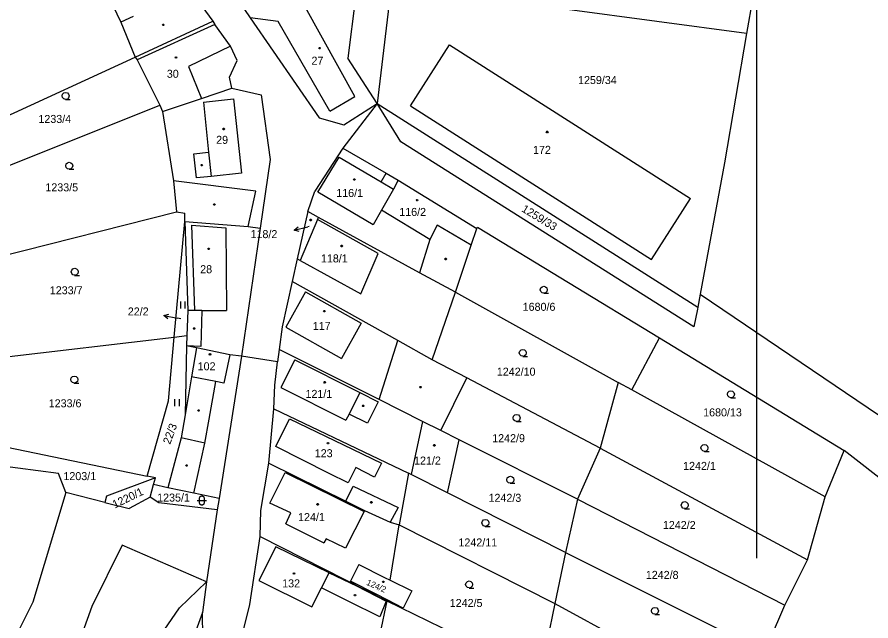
# Model space of a CAD drawing. Extents: x -802857 to -799647, y -1020285 to -1015884.
# Drawn here: x -801407 to -801225.7, y -1018013.3 to -1017885.2 of the extents above; entities that cross this region are included whole.
import ezdxf

# ---------------------------------------------------------------- set-up
doc = ezdxf.new("R2010")
doc.units = 0
for name, color, linetype in [('Default', 7, 'Continuous'), ('KLADY_ZMVM', 7, 'Continuous'), ('KN_HRANICE', 7, 'Continuous'), ('KN_KULTURY', 7, 'Continuous'), ('KN_PARCELY', 7, 'Continuous'), ('KN_SLUCKY', 7, 'Continuous')]:
    doc.layers.add(name, color=color, linetype=linetype)

# ---------------------------------------------------------------- blocks, each defined once
blk = doc.blocks.new('304')
at = {"layer": 'Default'}
blk.add_lwpolyline([(0, 0), (-0.38, 0.1), (-0.65, 0.37), (-0.75, 0.74), (-0.65, 1.11), (-0.38, 1.38), (-0.01, 1.48), (0.36, 1.38), (0.63, 1.11), (0.73, 0.73), (0.63, 0.35), (0.36, 0.08), (-0.02, -0.02), (0.98, -0.02)], dxfattribs=at)
blk = doc.blocks.new('306')
at = {"layer": 'Default'}
for p, q in [((-0.5, 1.5), (-0.5, 0)), ((0.5, 0), (0.5, 1.5))]:
    blk.add_line(p, q, dxfattribs=at)
blk = doc.blocks.new('316')
at = {"layer": 'Default'}
for points in [[(-0.5, 1.5), (-0.4, 1.79), (-0.15, 1.97), (0.16, 1.97), (0.41, 1.79), (0.51, 1.5), (0.51, 0.5), (0.41, 0.21), (0.16, 0.03), (-0.15, 0.03), (-0.4, 0.21), (-0.5, 0.5), (-0.5, 1.5)], [(-1, 1), (0.27, 1), (1, 1)]]:
    blk.add_lwpolyline(points, dxfattribs=at)
blk = doc.blocks.new('NAHRADNI_SYMBOL')
at = {"layer": 'Default'}
blk.add_lwpolyline([(0.09, 0.15), (0.18, 0), (0.09, -0.15), (-0.09, -0.15), (-0.18, 0), (-0.09, 0.15), (0.09, 0.15)], dxfattribs=at)
blk = doc.blocks.new('10292')
at = {"layer": 'Default'}
blk.add_line((0, 3), (0, 0), dxfattribs=at)
blk.add_lwpolyline([(-0.5, 2), (0, 3), (0.5, 2)], dxfattribs=at)
blk = doc.blocks.new('402')
at = {"layer": 'Default'}
blk.add_lwpolyline([(0.09, 0.15), (0.18, 0), (0.09, -0.15), (-0.09, -0.15), (-0.18, 0), (-0.09, 0.15), (0.09, 0.15)], dxfattribs=at)

msp = doc.modelspace()

# ---------------------------------------------------------------- linework, layer by layer
at = {"layer": 'KLADY_ZMVM'}
msp.add_lwpolyline([(-801250, -1017000), (-801250, -1017500), (-801250, -1018000)], dxfattribs=at)
at = {"layer": 'KN_HRANICE'}
for p, q in [((-801333.53, -1017868.36), (-801336.82, -1017893.87)), ((-801249.45, -1017873.01), (-801252.11, -1017888.65)), ((-801327.56, -1017878.51), (-801330.54, -1017903.51)), ((-801252.11, -1017888.65), (-801327.56, -1017878.51)), ((-801387.94, -1017879.91), (-801384.99, -1017886.23)), ((-801370.22, -1017879.44), (-801365.46, -1017886.06)), ((-801358.71, -1017883.58), (-801357.53, -1017885.3)), ((-801384.99, -1017886.23), (-801381.92, -1017893.65)), ((-801365.46, -1017886.06), (-801365.03, -1017886.71)), ((-801357.53, -1017885.3), (-801342.89, -1017906.53)), ((-801365.03, -1017886.71), (-801381.54, -1017894.26)), ((-801361.74, -1017891.36), (-801365.03, -1017886.71)), ((-801252.11, -1017888.65), (-801256.79, -1017916.12)), ((-801360.26, -1017894.37), (-801361.74, -1017891.36)), ((-801323.48, -1017904.01), (-801315.22, -1017891.06)), ((-801315.22, -1017891.06), (-801264.04, -1017923.7)), ((-801414.45, -1017908.61), (-801381.92, -1017893.65)), ((-801381.92, -1017893.65), (-801381.54, -1017894.26)), ((-801381.54, -1017894.26), (-801376.7, -1017903.9)), ((-801361.91, -1017897.94), (-801360.26, -1017894.37)), ((-801330.54, -1017903.51), (-801336.82, -1017893.87)), ((-801361.41, -1017900.25), (-801361.91, -1017897.94)), ((-801367.85, -1017902.42), (-801361.41, -1017900.25)), ((-801361.41, -1017900.25), (-801355.21, -1017901.66)), ((-801376.18, -1017905.18), (-801367.85, -1017902.42)), ((-801355.21, -1017901.66), (-801353.31, -1017915.4)), ((-801416.02, -1017919.61), (-801376.7, -1017903.9)), ((-801376.7, -1017903.9), (-801376.18, -1017905.18)), ((-801330.54, -1017903.51), (-801337.83, -1017912.98)), ((-801337.61, -1017908.03), (-801330.54, -1017903.51)), ((-801325.53, -1017911.62), (-801330.54, -1017903.51)), ((-801330.54, -1017903.51), (-801262.48, -1017946.77)), ((-801323.48, -1017904.01), (-801272.3, -1017936.65)), ((-801376.18, -1017905.18), (-801373.8, -1017919.91)), ((-801342.89, -1017906.53), (-801337.61, -1017908.03)), ((-801263.28, -1017950.94), (-801325.53, -1017911.62)), ((-801337.83, -1017912.98), (-801343.79, -1017922.09)), ((-801337.83, -1017912.98), (-801328.66, -1017918.31)), ((-801353.31, -1017915.4), (-801355.42, -1017929.99)), ((-801256.79, -1017916.12), (-801261.98, -1017943.96)), ((-801329.74, -1017920.15), (-801328.66, -1017918.31)), ((-801328.66, -1017918.31), (-801326.07, -1017919.82)), ((-801373.8, -1017919.91), (-801373.19, -1017926.53)), ((-801329.74, -1017920.15), (-801327.1, -1017921.71)), ((-801326.07, -1017919.82), (-801309.37, -1017930.06)), ((-801345.31, -1017926.43), (-801343.79, -1017922.09)), ((-801327.1, -1017921.71), (-801329.63, -1017926.15)), ((-801272.3, -1017936.65), (-801264.04, -1017923.7)), ((-801319.36, -1017932.37), (-801329.63, -1017926.15)), ((-801417.56, -1017937.72), (-801373.19, -1017926.53)), ((-801373.19, -1017926.53), (-801371.41, -1017926.77)), ((-801371.42, -1017928.53), (-801371.41, -1017926.77)), ((-801345.31, -1017926.43), (-801347.54, -1017936.5)), ((-801343.21, -1017928.17), (-801346.9, -1017936.85)), ((-801342.99, -1017927.7), (-801345.31, -1017926.43)), ((-801343.21, -1017928.17), (-801342.99, -1017927.7)), ((-801321.54, -1017939.43), (-801342.99, -1017927.7)), ((-801373.64, -1017953.09), (-801371.42, -1017928.53)), ((-801371.42, -1017928.53), (-801357.93, -1017929.6)), ((-801371.42, -1017928.53), (-801370.74, -1017947.44)), ((-801355.42, -1017929.99), (-801359.36, -1017957.14)), ((-801357.93, -1017929.6), (-801355.42, -1017929.99)), ((-801317.8, -1017929.31), (-801319.36, -1017932.37)), ((-801310.57, -1017933.62), (-801317.8, -1017929.31)), ((-801309.37, -1017930.06), (-801309.25, -1017929.73)), ((-801309.25, -1017929.73), (-801270.61, -1017953.27)), ((-801310.57, -1017933.62), (-801309.37, -1017930.06)), ((-801313.94, -1017943.59), (-801310.57, -1017933.62)), ((-801347.54, -1017936.5), (-801348.61, -1017941.32)), ((-801346.9, -1017936.85), (-801347.54, -1017936.5)), ((-801313.94, -1017943.59), (-801321.54, -1017939.43)), ((-801348.61, -1017941.32), (-801350.73, -1017950.9)), ((-801326.17, -1017953.84), (-801348.61, -1017941.32)), ((-801318.88, -1017957.91), (-801313.94, -1017943.59)), ((-801313.94, -1017943.59), (-801279.37, -1017962.72)), ((-801261.98, -1017943.96), (-801262.48, -1017946.77)), ((-801261.98, -1017943.96), (-801198.39, -1017987.04)), ((-801370.74, -1017947.44), (-801370.95, -1017952.78)), ((-801262.55, -1017947.15), (-801263.28, -1017950.94)), ((-801262.48, -1017946.77), (-801262.55, -1017947.15)), ((-801350.73, -1017950.9), (-801351.38, -1017955.73)), ((-801419.31, -1017958.41), (-801373.64, -1017953.09)), ((-801374.87, -1017966.64), (-801373.64, -1017953.09)), ((-801373.64, -1017953.09), (-801370.95, -1017952.78)), ((-801370.95, -1017952.78), (-801371.03, -1017954.93)), ((-801276.5, -1017964.31), (-801270.61, -1017953.27)), ((-801270.61, -1017953.27), (-801231.39, -1017977.16)), ((-801371.03, -1017954.93), (-801371.36, -1017969.59)), ((-801368.92, -1017955.35), (-801371.03, -1017954.93)), ((-801361.84, -1017956.87), (-801368.92, -1017955.35)), ((-801318.88, -1017957.91), (-801326.17, -1017953.84)), ((-801359.36, -1017957.14), (-801364.13, -1017987.34)), ((-801359.36, -1017957.14), (-801361.84, -1017956.87)), ((-801351.73, -1017958.32), (-801359.36, -1017957.14)), ((-801351.38, -1017955.73), (-801351.73, -1017958.32)), ((-801330.17, -1017966.36), (-801351.38, -1017955.73)), ((-801352.32, -1017963.31), (-801351.73, -1017958.32)), ((-801311.5, -1017961.78), (-801318.88, -1017957.91)), ((-801317.05, -1017972.94), (-801311.5, -1017961.78)), ((-801283.17, -1017976.65), (-801311.5, -1017961.78)), ((-801352.51, -1017968.31), (-801352.32, -1017963.31)), ((-801279.37, -1017962.72), (-801283.17, -1017976.65)), ((-801276.5, -1017964.31), (-801279.37, -1017962.72)), ((-801235.44, -1017987.03), (-801276.5, -1017964.31)), ((-801379.38, -1017982.63), (-801374.87, -1017966.64)), ((-801320.94, -1017970.99), (-801330.17, -1017966.36)), ((-801371.36, -1017969.59), (-801372.21, -1017974.52)), ((-801353.58, -1017979.89), (-801352.51, -1017968.31)), ((-801352.51, -1017968.31), (-801323.93, -1017982)), ((-801320.94, -1017970.99), (-801323.35, -1017982.29)), ((-801317.05, -1017972.94), (-801320.94, -1017970.99)), ((-801313.17, -1017974.89), (-801317.05, -1017972.94)), ((-801420.83, -1017974.05), (-801379.38, -1017982.63)), ((-801372.21, -1017974.52), (-801375.02, -1017985.09)), ((-801315.64, -1017986.18), (-801313.17, -1017974.89)), ((-801288.02, -1017987.5), (-801313.17, -1017974.89)), ((-801283.17, -1017976.65), (-801288.02, -1017987.5)), ((-801283.17, -1017976.65), (-801239.16, -1018000.38)), ((-801235.44, -1017987.03), (-801231.39, -1017977.16)), ((-801209.9, -1017994.03), (-801231.39, -1017977.16)), ((-801398.22, -1017982.04), (-801421.32, -1017979.03)), ((-801355.23, -1017989.94), (-801353.58, -1017979.89)), ((-801353.58, -1017979.89), (-801337.21, -1017987.91)), ((-801396.64, -1017986.09), (-801398.22, -1017982.04)), ((-801323.93, -1017982), (-801325.88, -1017992.98)), ((-801323.35, -1017982.29), (-801323.93, -1017982)), ((-801315.64, -1017986.18), (-801323.35, -1017982.29)), ((-801377.64, -1017982.98), (-801388.03, -1017986.86)), ((-801377.64, -1017982.98), (-801379.38, -1017982.63)), ((-801378.76, -1017987.09), (-801378.04, -1017984.42)), ((-801378.04, -1017984.42), (-801377.64, -1017982.98)), ((-801375.02, -1017985.09), (-801378.04, -1017984.42)), ((-801396.64, -1017986.09), (-801403.7, -1018009.39)), ((-801388.4, -1017988.19), (-801396.64, -1017986.09)), ((-801369.47, -1017986.2), (-801375.02, -1017985.09)), ((-801364.13, -1017987.34), (-801369.47, -1017986.2)), ((-801290.6, -1017998.81), (-801315.64, -1017986.18)), ((-801388.03, -1017986.86), (-801388.4, -1017988.19)), ((-801378.76, -1017987.09), (-801383.2, -1017989.51)), ((-801376.96, -1017988.29), (-801378.76, -1017987.09)), ((-801364.13, -1017987.34), (-801364.52, -1017989.8)), ((-801337.21, -1017987.91), (-801333.24, -1017989.93)), ((-801288.02, -1017987.5), (-801290.6, -1017998.81)), ((-801288.02, -1017987.5), (-801243.96, -1018010)), ((-801239.16, -1018000.38), (-801235.44, -1017987.03)), ((-801388.4, -1017988.19), (-801383.2, -1017989.51)), ((-801364.52, -1017989.8), (-801376.96, -1017988.29)), ((-801364.52, -1017989.8), (-801366.8, -1018005.03)), ((-801355.39, -1017995.42), (-801355.23, -1017989.94)), ((-801333.24, -1017989.93), (-801327.78, -1017992.36)), ((-801327.78, -1017992.36), (-801325.88, -1017992.98)), ((-801327.78, -1018004.7), (-801325.88, -1017992.98)), ((-801325.88, -1017992.98), (-801292.85, -1018009.68)), ((-801357.6, -1018009.88), (-801355.39, -1017995.42)), ((-801355.39, -1017995.42), (-801328.49, -1018009.09)), ((-801384.72, -1017997.28), (-801391.12, -1018010.28)), ((-801366.8, -1018005.03), (-801384.72, -1017997.28)), ((-801290.6, -1017998.81), (-801292.85, -1018009.68)), ((-801290.6, -1017998.81), (-801248.25, -1018019.94)), ((-801243.96, -1018010), (-801239.16, -1018000.38)), ((-801334.42, -1018001.35), (-801336.22, -1018004.93)), ((-801334.42, -1018001.35), (-801328.98, -1018004.1)), ((-801328.98, -1018004.1), (-801327.78, -1018004.7)), ((-801372.53, -1018010.6), (-801366.8, -1018005.03)), ((-801366.8, -1018005.03), (-801367.65, -1018011.57)), ((-801330.78, -1018007.67), (-801336.22, -1018004.93)), ((-801327.78, -1018004.7), (-801323.22, -1018006.97)), ((-801328.46, -1018008.88), (-801330.78, -1018007.67)), ((-801323.22, -1018006.97), (-801325.07, -1018010.63)), ((-801403.7, -1018009.39), (-801421.73, -1018045.46)), ((-801328.49, -1018009.09), (-801329.99, -1018016.14)), ((-801328.49, -1018009.09), (-801328.46, -1018008.88)), ((-801328.49, -1018009.09), (-801295.95, -1018024.91)), ((-801325.07, -1018010.63), (-801328.46, -1018008.88)), ((-801292.85, -1018009.68), (-801295.95, -1018024.91)), ((-801292.85, -1018009.68), (-801252.58, -1018031.49)), ((-801391.12, -1018010.28), (-801402.79, -1018042.66)), ((-801384.44, -1018027.77), (-801372.53, -1018010.6)), ((-801367.65, -1018011.57), (-801380.88, -1018048.02)), ((-801367.61, -1018016.94), (-801367.65, -1018011.57)), ((-801360.46, -1018021.5), (-801357.6, -1018009.88)), ((-801248.25, -1018019.94), (-801243.96, -1018010))]:
    msp.add_line(p, q, dxfattribs=at)
at = {"layer": 'KN_PARCELY'}
for p, q in [((-801344.98, -1017929.64), (-801345.28, -1017929.71)), ((-801372.24, -1017949.24), (-801372.94, -1017949.1))]:
    msp.add_line(p, q, dxfattribs=at)
at = {"layer": 'KN_SLUCKY'}
for p, q in [((-801335.32, -1017902), (-801345.75, -1017883.16)), ((-801382.41, -1017885.03), (-801384.99, -1017886.23)), ((-801381.92, -1017893.65), (-801365.46, -1017886.06)), ((-801351.55, -1017886.13), (-801357.53, -1017885.3)), ((-801340.59, -1017905.11), (-801351.55, -1017886.13)), ((-801361.74, -1017891.36), (-801370.6, -1017895.68)), ((-801370.6, -1017895.68), (-801367.85, -1017902.42)), ((-801367.47, -1017903.23), (-801361.05, -1017902.52)), ((-801361.05, -1017902.52), (-801359.4, -1017918.31)), ((-801340.59, -1017905.11), (-801335.32, -1017902)), ((-801367.47, -1017903.23), (-801366.36, -1017913.86)), ((-801369.48, -1017914.19), (-801366.36, -1017913.86)), ((-801368.95, -1017919.31), (-801369.48, -1017914.19)), ((-801366.36, -1017913.86), (-801365.82, -1017918.98)), ((-801343.14, -1017922.3), (-801338.66, -1017914.88)), ((-801338.66, -1017914.88), (-801329.74, -1017920.15)), ((-801365.82, -1017918.98), (-801368.95, -1017919.31)), ((-801359.4, -1017918.31), (-801365.82, -1017918.98)), ((-801356.36, -1017922.11), (-801373.8, -1017919.91)), ((-801326.07, -1017919.82), (-801327.1, -1017921.71)), ((-801357.93, -1017929.6), (-801356.36, -1017922.11)), ((-801331.42, -1017929.24), (-801343.14, -1017922.3)), ((-801329.63, -1017926.15), (-801331.42, -1017929.24)), ((-801330.33, -1017935.36), (-801343.21, -1017928.17)), ((-801369.97, -1017929.35), (-801362.72, -1017929.9)), ((-801369.97, -1017929.35), (-801369.36, -1017947.45)), ((-801362.72, -1017929.9), (-801362.59, -1017947.45)), ((-801319.36, -1017932.37), (-801321.54, -1017939.43)), ((-801334, -1017943.9), (-801330.33, -1017935.36)), ((-801346.9, -1017936.85), (-801334, -1017943.9)), ((-801345.81, -1017943.46), (-801349.97, -1017950.96)), ((-801345.81, -1017943.46), (-801333.95, -1017950.12)), ((-801369.36, -1017947.45), (-801370.74, -1017947.44)), ((-801367.8, -1017947.47), (-801369.36, -1017947.45)), ((-801367.8, -1017947.47), (-801368.03, -1017955.07)), ((-801367.8, -1017947.47), (-801362.59, -1017947.45)), ((-801349.97, -1017950.96), (-801338.11, -1017957.62)), ((-801333.95, -1017950.12), (-801338.11, -1017957.62)), ((-801368.03, -1017955.07), (-801371.03, -1017954.93)), ((-801368.92, -1017955.35), (-801369.98, -1017961.56)), ((-801330.17, -1017966.36), (-801326.17, -1017953.84)), ((-801361.84, -1017956.87), (-801363.1, -1017962.87)), ((-801348.05, -1017957.96), (-801351.05, -1017963.8)), ((-801348.05, -1017957.96), (-801334.27, -1017964.86)), ((-801369.98, -1017961.56), (-801371.36, -1017969.59)), ((-801364.8, -1017962.55), (-801369.98, -1017961.56)), ((-801366.26, -1017970.53), (-801364.8, -1017962.55)), ((-801363.1, -1017962.87), (-801364.8, -1017962.55)), ((-801351.05, -1017963.8), (-801337.19, -1017970.74)), ((-801334.27, -1017964.86), (-801336.54, -1017969.43)), ((-801334.27, -1017964.86), (-801330.32, -1017966.84)), ((-801330.32, -1017966.84), (-801332.6, -1017971.4)), ((-801336.54, -1017969.43), (-801337.19, -1017970.74)), ((-801332.6, -1017971.4), (-801336.54, -1017969.43)), ((-801367.19, -1017975.61), (-801366.26, -1017970.53)), ((-801352.09, -1017976.3), (-801349.15, -1017970.42)), ((-801349.15, -1017970.42), (-801337.69, -1017975.98)), ((-801367.19, -1017975.61), (-801372.21, -1017974.52)), ((-801369.47, -1017986.2), (-801367.19, -1017975.61)), ((-801340.76, -1017982.03), (-801352.09, -1017976.3)), ((-801337.69, -1017975.98), (-801329.66, -1017979.87)), ((-801329.66, -1017979.87), (-801331.16, -1017982.8)), ((-801353.36, -1017988.32), (-801350.11, -1017981.87)), ((-801350.11, -1017981.87), (-801333.33, -1017990.11)), ((-801336.74, -1017984.06), (-801340.76, -1017982.03)), ((-801335.11, -1017980.8), (-801336.74, -1017984.06)), ((-801331.16, -1017982.8), (-801335.11, -1017980.8)), ((-801337.21, -1017987.91), (-801335.63, -1017984.73)), ((-801335.63, -1017984.73), (-801326.12, -1017989.25)), ((-801348.9, -1017990.41), (-801353.36, -1017988.32)), ((-801326.12, -1017989.25), (-801327.78, -1017992.36)), ((-801349.97, -1017992.75), (-801348.9, -1017990.41)), ((-801333.33, -1017990.11), (-801337.28, -1017997.9)), ((-801349.97, -1017992.75), (-801345.71, -1017994.87)), ((-801345.71, -1017994.87), (-801341.88, -1017996.78)), ((-801341.42, -1017995.92), (-801341.88, -1017996.78)), ((-801337.28, -1017997.9), (-801341.42, -1017995.92)), ((-801352.07, -1017997.62), (-801355.72, -1018004.74)), ((-801340.74, -1018003.13), (-801352.07, -1017997.62)), ((-801342.37, -1018006.35), (-801340.74, -1018003.13)), ((-801340.74, -1018003.13), (-801334.97, -1018005.93)), ((-801355.72, -1018004.74), (-801344.44, -1018010.35)), ((-801334.97, -1018005.93), (-801328.64, -1018009.13)), ((-801344.44, -1018010.35), (-801342.37, -1018006.35)), ((-801336.6, -1018009.2), (-801342.37, -1018006.35)), ((-801329.97, -1018012.48), (-801336.6, -1018009.2)), ((-801328.64, -1018009.13), (-801329.97, -1018012.48))]:
    msp.add_line(p, q, dxfattribs=at)

# ---------------------------------------------------------------- block references
at = {"layer": 'KN_KULTURY'}
for name, p in [('402', (-801375.99, -1017886.81)), ('402', (-801342.8, -1017891.76)), ('402', (-801373.27, -1017893.72)), ('304', (-801396.71, -1017902.64)), ('402', (-801363.17, -1017908.92)), ('402', (-801294.46, -1017909.56)), ('304', (-801395.94, -1017917.46)), ('402', (-801367.81, -1017916.59)), ('402', (-801335.39, -1017919.64)), ('402', (-801322.07, -1017924.01)), ('402', (-801365.15, -1017924.93)), ('NAHRADNI_SYMBOL', (-801344.7, -1017928.24)), ('402', (-801338.1, -1017933.77)), ('402', (-801366.36, -1017934.37)), ('402', (-801316, -1017936.53)), ('304', (-801394.78, -1017939.97)), ('304', (-801295.17, -1017943.78)), ('306', (-801371.85, -1017947.05)), ('402', (-801341.78, -1017947.62)), ('402', (-801369.42, -1017951.29)), ('402', (-801366.05, -1017956.76)), ('304', (-801299.63, -1017957.18)), ('304', (-801394.86, -1017962.85)), ('402', (-801341.68, -1017962.7)), ('402', (-801321.36, -1017963.73)), ('306', (-801373.07, -1017967.79)), ('304', (-801255.44, -1017965.97)), ('402', (-801333.53, -1017967.69)), ('402', (-801368.49, -1017968.66)), ('304', (-801300.94, -1017971)), ('402', (-801340.99, -1017975.62)), ('402', (-801318.43, -1017976.08)), ('304', (-801261.04, -1017977.36)), ('402', (-801371.04, -1017980.37)), ('304', (-801302.27, -1017984.11)), ('316', (-801367.81, -1017988.8)), ('402', (-801331.79, -1017988.17)), ('304', (-801265.24, -1017989.51)), ('402', (-801343.21, -1017988.6)), ('304', (-801307.57, -1017993.28)), ('402', (-801348.24, -1018003.31)), ('402', (-801329.26, -1018005.04)), ('304', (-801311.03, -1018006.35)), ('402', (-801335.25, -1018007.87)), ('304', (-801271.56, -1018011.95))]:
    msp.add_blockref(name, p, dxfattribs=at)
at = {"layer": 'KN_PARCELY'}
for p, rotation in [((-801345.28, -1017929.71), 103.132403), ((-801372.94, -1017949.1), 78.667105)]:
    msp.add_blockref('10292', p, dxfattribs=dict(at, rotation=rotation))

# ---------------------------------------------------------------- texts
for s, height, p in [('27', 1.7, (-801344.51, -1017895.28)), ('30', 1.7, (-801375.23, -1017898.05)), ('1259/34', 1.7, (-801287.9, -1017899.38)), ('1233/4', 1.7, (-801402.5, -1017907.64)), ('29', 1.7, (-801364.75, -1017912.07)), ('172', 1.7, (-801297.46, -1017914.2)), ('1233/5', 1.7, (-801401.02, -1017922.16)), ('116/1', 1.7, (-801339.25, -1017923.36)), ('116/2', 1.7, (-801325.87, -1017927.38)), ('118/2', 0.1, (-801345.23, -1017929.64)), ('118/2', 1.7, (-801357.45, -1017932.09)), ('118/1', 1.7, (-801342.5, -1017937.25)), ('28', 1.7, (-801368.14, -1017939.54)), ('1233/7', 1.7, (-801400.08, -1017944.01)), ('1680/6', 1.7, (-801299.66, -1017947.52)), ('22/2', 1.7, (-801383.52, -1017948.51)), ('22/2', 0.1, (-801372.44, -1017949.24)), ('117', 1.7, (-801344.23, -1017951.58)), ('102', 1.7, (-801368.68, -1017960.15)), ('1242/10', 1.7, (-801305.15, -1017961.29)), ('121/1', 1.7, (-801345.78, -1017966.01)), ('1233/6', 1.7, (-801400.31, -1017968)), ('1680/13', 1.7, (-801261.33, -1017969.93)), ('1242/9', 1.7, (-801306.13, -1017975.41)), ('123', 1.7, (-801343.81, -1017978.6)), ('121/2', 1.7, (-801322.72, -1017980.16)), ('1242/1', 1.7, (-801265.59, -1017981.29)), ('1203/1', 1.7, (-801397.19, -1017983.46)), ('1235/1', 1.7, (-801377.28, -1017988.02)), ('1242/3', 1.7, (-801306.91, -1017988.07)), ('124/1', 1.7, (-801347.36, -1017992.15)), ('1242/2', 1.7, (-801269.88, -1017993.84)), ('1242/11', 1.7, (-801313.3, -1017997.54)), ('1242/8', 1.7, (-801273.51, -1018004.43)), ('132', 1.7, (-801350.73, -1018006.23)), ('1242/5', 1.7, (-801315.15, -1018010.39))]:
    msp.add_text(s, height=height, dxfattribs=at).set_placement(p)
for s, height, rotation, p in [('1259/33', 1.7, 328.591, (-801300.05, -1017926.32)), ('22/3', 1.7, 70.015, (-801374.52, -1017975.98)), ('1220/1', 1.7, 25.783, (-801386.28, -1017989.5)), ('124/2', 1.29, 336.269, (-801332.96, -1018005.65))]:
    msp.add_text(s, height=height, rotation=rotation, dxfattribs=at).set_placement(p)

doc.saveas('drawing.dxf')
